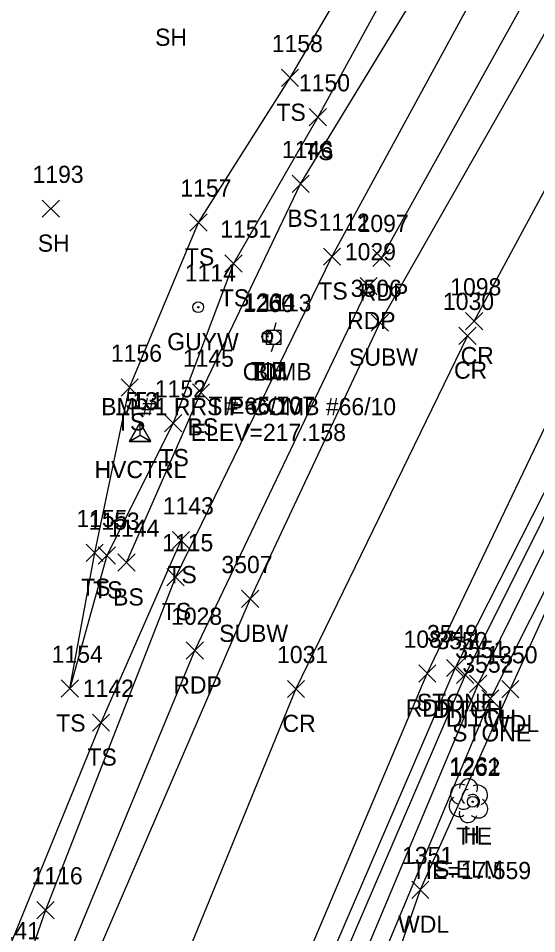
# Model space of a CAD drawing. Extents: x 1634209 to 1639641, y 608564 to 612258.
# Drawn here: x 1639421.2 to 1639481.5, y 611953 to 612059.5 of the extents above; entities that cross this region are included whole.
import ezdxf

# ---------------------------------------------------------------- set-up
doc = ezdxf.new("R2010")
doc.units = 0
for name, color, linetype in [('C_A', 7, 'Continuous'), ('C_C', 7, 'Continuous'), ('C_I', 7, 'Continuous'), ('CBP', 7, 'Continuous'), ('CPBM', 7, 'Continuous'), ('CPSM', 7, 'Continuous'), ('D_A', 7, 'Continuous'), ('D_I', 7, 'Continuous'), ('D_TIC', 7, 'Continuous'), ('DD', 7, 'Continuous'), ('L_A', 7, 'Continuous'), ('L_C', 7, 'Continuous'), ('L_I', 7, 'Continuous'), ('L_TIC', 7, 'Continuous'), ('LASF', 7, 'Continuous'), ('LAWA', 7, 'Continuous'), ('LELB', 7, 'Continuous'), ('LTD', 7, 'Continuous'), ('P_A', 7, 'Continuous'), ('P_I', 7, 'Continuous'), ('P_TIC', 7, 'Continuous'), ('PET', 7, 'Continuous'), ('PRC', 7, 'Continuous'), ('U_A', 7, 'Continuous'), ('U_C', 7, 'Continuous'), ('U_I', 7, 'Continuous'), ('U_TIC', 7, 'Continuous'), ('UP', 7, 'Continuous'), ('UPGW', 7, 'Continuous'), ('UW', 7, 'Continuous')]:
    doc.layers.add(name, color=color, linetype=linetype)

msp = doc.modelspace()

# ---------------------------------------------------------------- linework, layer by layer
at = {"layer": 'CBP'}
for centre, radius in [((1639450.18, 612022.46), 0.625), ((1639450.18, 612022.46), 0.0833), ((1639474.1, 611968.33), 0.625), ((1639474.1, 611968.33), 0.0833)]:
    msp.add_circle(centre, radius, dxfattribs=at)
at = {"layer": 'CPBM'}
for p, q in [((1639449.67, 612021.79), (1639449.67, 612022.79)), ((1639449.67, 612022.79), (1639450.67, 612022.79)), ((1639450.67, 612022.79), (1639450.67, 612021.79)), ((1639450.67, 612021.79), (1639449.67, 612021.79)), ((1639450.17, 612022.29), (1639450.17, 612022.29)), ((1639450.17, 612022.29), (1639450.17, 612022.29))]:
    msp.add_line(p, q, dxfattribs=at)
at = {"layer": 'CPSM'}
for p, q in [((1639434.12, 612010.25), (1639435.37, 612012.42)), ((1639434.13, 612010.26), (1639435.38, 612012.43)), ((1639434.13, 612010.26), (1639435.38, 612012.43)), ((1639436.62, 612010.25), (1639435.37, 612012.42)), ((1639435.37, 612010.97), (1639435.37, 612012.42)), ((1639436.63, 612010.26), (1639435.38, 612012.43)), ((1639435.38, 612010.98), (1639435.38, 612012.43)), ((1639436.63, 612010.26), (1639435.38, 612012.43)), ((1639435.38, 612010.98), (1639435.38, 612012.43)), ((1639434.12, 612010.25), (1639435.37, 612010.97)), ((1639434.12, 612010.25), (1639436.62, 612010.25)), ((1639434.13, 612010.26), (1639435.38, 612010.98)), ((1639434.13, 612010.26), (1639435.38, 612010.98)), ((1639434.13, 612010.26), (1639436.63, 612010.26)), ((1639434.13, 612010.26), (1639436.63, 612010.26)), ((1639435.37, 612010.97), (1639435.37, 612010.97)), ((1639435.37, 612010.97), (1639436.62, 612010.25)), ((1639435.38, 612010.98), (1639435.38, 612010.98)), ((1639435.38, 612010.98), (1639436.63, 612010.26)), ((1639435.38, 612010.98), (1639435.38, 612010.98)), ((1639435.38, 612010.98), (1639436.63, 612010.26))]:
    msp.add_line(p, q, dxfattribs=at)
at = {"layer": 'D_TIC'}
for points in [[(1639472.22, 611982.07), (1639474.22, 611984.07)], [(1639474.22, 611982.07), (1639472.22, 611984.07)], [(1639473.74, 611981.05), (1639475.74, 611983.05)], [(1639475.74, 611981.05), (1639473.74, 611983.05)]]:
    msp.add_lwpolyline(points, dxfattribs=at)
at = {"layer": 'DD'}
for points in [[(1639560.57, 612129.01), (1639556.53, 612119.06), (1639548.81, 612104.26), (1639529.12, 612083.62), (1639507.53, 612047.31), (1639491.18, 612019.02), (1639473.22, 611983.07), (1639456.59, 611944.52), (1639441.68, 611899.83), (1639426.6, 611855.12), (1639414, 611809.64), (1639403.11, 611769.87), (1639390.43, 611727.49), (1639379.87, 611693.81), (1639369.1, 611662.09), (1639367.84, 611659.83)], [(1639561.94, 612128.14), (1639558.11, 612117.59), (1639549.56, 612103.15), (1639530.32, 612082.73), (1639508.94, 612046.64), (1639492.68, 612018.5), (1639474.74, 611982.05), (1639458.96, 611944.55), (1639442.97, 611899.33), (1639428.64, 611854.96), (1639415.08, 611808.28), (1639405.32, 611769.46), (1639392.22, 611726.77), (1639382.52, 611693.71), (1639371.49, 611661), (1639370.19, 611658.57)]]:
    msp.add_lwpolyline(points, dxfattribs=at)
at = {"layer": 'L_TIC'}
for points in [[(1639451.83, 612051.53), (1639453.83, 612053.53)], [(1639453.83, 612051.53), (1639451.83, 612053.53)], [(1639455.07, 612046.96), (1639457.07, 612048.96)], [(1639457.07, 612046.96), (1639455.07, 612048.96)], [(1639453.06, 612039.2), (1639455.06, 612041.2)], [(1639455.06, 612039.2), (1639453.06, 612041.2)], [(1639423.98, 612036.31), (1639425.98, 612038.31)], [(1639425.98, 612036.31), (1639423.98, 612038.31)], [(1639441.18, 612034.71), (1639443.18, 612036.71)], [(1639443.18, 612034.71), (1639441.18, 612036.71)], [(1639456.71, 612030.74), (1639458.71, 612032.74)], [(1639458.71, 612030.74), (1639456.71, 612032.74)], [(1639445.25, 612029.94), (1639447.25, 612031.94)], [(1639447.25, 612029.94), (1639445.25, 612031.94)], [(1639433.15, 612015.51), (1639435.15, 612017.51)], [(1639435.15, 612015.51), (1639433.15, 612017.51)], [(1639441.46, 612014.93), (1639443.46, 612016.93)], [(1639443.46, 612014.93), (1639441.46, 612016.93)], [(1639438.22, 612011.36), (1639440.22, 612013.36)], [(1639440.22, 612011.36), (1639438.22, 612013.36)], [(1639439.14, 611997.75), (1639441.14, 611999.75)], [(1639441.14, 611997.75), (1639439.14, 611999.75)], [(1639429.09, 611996.28), (1639431.09, 611998.28)], [(1639431.09, 611996.28), (1639429.09, 611998.28)], [(1639430.5, 611995.97), (1639432.5, 611997.97)], [(1639432.5, 611995.97), (1639430.5, 611997.97)], [(1639432.79, 611995.15), (1639434.79, 611997.15)], [(1639434.79, 611995.15), (1639432.79, 611997.15)], [(1639438.5, 611993.46), (1639440.5, 611995.46)], [(1639440.5, 611993.46), (1639438.5, 611995.46)], [(1639471.04, 611982.89), (1639473.04, 611984.89)], [(1639473.04, 611982.89), (1639471.04, 611984.89)], [(1639426.2, 611980.49), (1639428.2, 611982.49)], [(1639428.2, 611980.49), (1639426.2, 611982.49)], [(1639477.47, 611980.43), (1639479.47, 611982.43)], [(1639479.47, 611980.43), (1639477.47, 611982.43)], [(1639475.15, 611979.34), (1639477.15, 611981.34)], [(1639477.15, 611979.34), (1639475.15, 611981.34)], [(1639429.83, 611976.53), (1639431.83, 611978.53)], [(1639431.83, 611976.53), (1639429.83, 611978.53)], [(1639466.99, 611957.08), (1639468.99, 611959.08)], [(1639468.99, 611957.08), (1639466.99, 611959.08)], [(1639423.36, 611954.72), (1639425.36, 611956.72)], [(1639425.36, 611954.72), (1639423.36, 611956.72)]]:
    msp.add_lwpolyline(points, dxfattribs=at)
at = {"layer": 'LASF'}
for points in [[(1639558.56, 612130.45), (1639552.86, 612120.18), (1639541.01, 612102.18), (1639527.49, 612085.59), (1639505.85, 612048.28), (1639489.98, 612019.2), (1639472.04, 611983.89), (1639455.22, 611944.85), (1639439.42, 611901.14), (1639424.97, 611855.61), (1639411.65, 611810.44), (1639400.31, 611769.99), (1639387.4, 611727.33), (1639377.22, 611693.8), (1639367.21, 611662.75), (1639359.89, 611644.2)], [(1639564.17, 612127.3), (1639559.55, 612115.01), (1639546.48, 612097.15), (1639532.98, 612081.91), (1639511.96, 612045.66), (1639494.66, 612017.18), (1639476.15, 611980.34), (1639460.76, 611943.45), (1639444.67, 611898.59), (1639430.04, 611853.19), (1639417.13, 611807.26), (1639407.25, 611767.41), (1639395.02, 611725.74), (1639384.78, 611692.04), (1639373.34, 611660.29), (1639366.81, 611640.98)]]:
    msp.add_lwpolyline(points, dxfattribs=at)
at = {"layer": 'LAWA'}
msp.add_lwpolyline([(1639621.29, 612162.67), (1639586.37, 612122.18), (1639574.47, 612128.38), (1639569.45, 612130.12), (1639568.95, 612119.64), (1639554.1, 612098.18), (1639539.81, 612087.62), (1639526.58, 612068.13), (1639518.72, 612053.78), (1639510.6, 612040.7), (1639492.01, 612011.11), (1639478.47, 611981.43), (1639467.99, 611958.08), (1639459.16, 611932.72), (1639452.06, 611918.05), (1639447.34, 611897.74), (1639441.05, 611876.68), (1639428.25, 611845.92)], dxfattribs=at)
at = {"layer": 'LELB'}
for points in [[(1639486.03, 612090.67), (1639466.52, 612067.04), (1639456.07, 612047.96), (1639446.25, 612030.94), (1639439.22, 612012.36), (1639431.5, 611996.97), (1639427.2, 611981.49), (1639430.09, 611997.28), (1639434.15, 612016.51), (1639442.18, 612035.71), (1639452.83, 612052.53), (1639468.37, 612078.96), (1639484.08, 612100.5), (1639508.75, 612130.39), (1639537.72, 612170.27), (1639559.87, 612201)], [(1639563.38, 612198.7), (1639539.24, 612164.06), (1639514.54, 612127.14), (1639495.77, 612095.8), (1639476.98, 612067.19), (1639457.71, 612031.74), (1639439.5, 611994.46), (1639424.36, 611955.72), (1639410.24, 611915.34), (1639396.62, 611874), (1639380.38, 611821.61)], [(1639433.79, 611996.15), (1639442.46, 612015.93), (1639454.06, 612040.2), (1639468.96, 612064.67)], [(1639383.1, 611838.36), (1639397.42, 611885.01), (1639407.84, 611916.5), (1639419.32, 611949.32), (1639430.83, 611977.53), (1639440.14, 611998.75)]]:
    msp.add_lwpolyline(points, dxfattribs=at)
at = {"layer": 'LTD'}
msp.add_line((1639473.57, 611968.49), (1639473.57, 611968.49), dxfattribs=at)
msp.add_line((1639473.57, 611968.49), (1639473.57, 611968.49), dxfattribs=at)
msp.add_arc((1639473.62, 611969.93), 1.05, 335.5272, 180.9563, dxfattribs=at)
for centre, major_axis, ratio, start_param, end_param in [((1639472.78, 611969.16), (1.21, -0.51), 0.895232, 1.570796, 4.712389), ((1639473.36, 611968.95), (-0.208, -0.792), 0.645439, 3.141593, 6.283185), ((1639474.61, 611969.08), (-1.14, -0.48), 0.949671, 1.570796, 4.712389), ((1639472.49, 611967.79), (0.58, -1.04), 0.959034, 3.141593, 6.283185), ((1639474.07, 611968.33), (-0.5, 0.667), 0.989748, 3.141593, 6.283185), ((1639474.57, 611967.66), (-1.09, 0.79), 0.841452, 1.570796, 4.712389), ((1639473.11, 611967.74), (-0.625, -0.083), 0.423636, 0, 3.141593), ((1639473.57, 611966.99), (0.26, 1.06), 0.942809, 1.570796, 4.712389)]:
    msp.add_ellipse(centre, major_axis=major_axis, ratio=ratio, start_param=start_param, end_param=end_param, dxfattribs=at)
at = {"layer": 'P_TIC'}
for points in [[(1639462.47, 612030.6), (1639464.47, 612032.6)], [(1639464.47, 612030.6), (1639462.47, 612032.6)], [(1639460.99, 612027.31), (1639462.99, 612029.31)], [(1639462.99, 612027.31), (1639460.99, 612029.31)], [(1639473.26, 612023.23), (1639475.26, 612025.23)], [(1639475.26, 612023.23), (1639473.26, 612025.23)], [(1639472.49, 612021.53), (1639474.49, 612023.53)], [(1639474.49, 612021.53), (1639472.49, 612023.53)], [(1639440.75, 611984.91), (1639442.75, 611986.91)], [(1639442.75, 611984.91), (1639440.75, 611986.91)], [(1639467.81, 611982.24), (1639469.81, 611984.24)], [(1639469.81, 611982.24), (1639467.81, 611984.24)], [(1639452.52, 611980.45), (1639454.52, 611982.45)], [(1639454.52, 611980.45), (1639452.52, 611982.45)]]:
    msp.add_lwpolyline(points, dxfattribs=at)
at = {"layer": 'PET'}
for points in [[(1639566.82, 612196.97), (1639540.89, 612159.33), (1639514.14, 612118.57), (1639490.67, 612080.46), (1639463.47, 612031.6)], [(1639245.26, 611428.04), (1639265.27, 611462.65), (1639285.72, 611496.98), (1639297.96, 611518.63), (1639312.46, 611545.86), (1639331.24, 611585.47), (1639351.91, 611632.95), (1639369.29, 611681.55), (1639385.15, 611732.94), (1639399.72, 611782.78), (1639415.55, 611836.4), (1639431.27, 611887.12), (1639449.51, 611937.71), (1639468.81, 611983.24), (1639484.71, 612016.46), (1639503.95, 612051.42), (1639527.63, 612090.72), (1639556.4, 612135.38), (1639588.32, 612182.52)], [(1639220.96, 611441.47), (1639247.22, 611483.75), (1639268.21, 611519.52), (1639285.57, 611551.38), (1639309.59, 611600.33), (1639328.5, 611645.78), (1639344.08, 611688.66), (1639358.64, 611735.43), (1639372.55, 611782.94), (1639389.96, 611841.92), (1639405.55, 611892.01), (1639422.64, 611939.83), (1639441.75, 611985.91), (1639461.99, 612028.31)]]:
    msp.add_lwpolyline(points, dxfattribs=at)
at = {"layer": 'PRC'}
for points in [[(1639474.26, 612024.23), (1639486.3, 612046.51), (1639504.13, 612077.19), (1639528.27, 612115.93), (1639556.35, 612158.67), (1639577.48, 612189.8)], [(1639473.49, 612022.53), (1639453.52, 611981.45), (1639432.7, 611930.67), (1639416.88, 611885.46), (1639401.13, 611834.82), (1639385.48, 611780.16), (1639369.66, 611726.72), (1639353.84, 611677.52), (1639335.57, 611627.61), (1639314.72, 611580.03), (1639292.65, 611536.14), (1639275.3, 611504.78), (1639250.46, 611462.84), (1639222.36, 611418.18)]]:
    msp.add_lwpolyline(points, dxfattribs=at)
at = {"layer": 'U_TIC'}
for points in [[(1639462.29, 612023.05), (1639464.29, 612025.05)], [(1639464.29, 612023.05), (1639462.29, 612025.05)], [(1639447.18, 611990.92), (1639449.18, 611992.92)], [(1639449.18, 611990.92), (1639447.18, 611992.92)]]:
    msp.add_lwpolyline(points, dxfattribs=at)
at = {"layer": 'UP'}
for p, q in [((1639451.18, 612024.02), (1639450.93, 612023.19)), ((1639450.1, 612021.52), (1639450.1, 612023.19)), ((1639450.1, 612023.19), (1639451.77, 612023.19)), ((1639451.77, 612023.19), (1639451.77, 612021.52)), ((1639450.93, 612022.36), (1639450.93, 612022.36)), ((1639451.77, 612021.52), (1639450.1, 612021.52)), ((1639450.68, 612020.69), (1639450.93, 612021.52))]:
    msp.add_line(p, q, dxfattribs=at)
msp.add_circle((1639450.93, 612022.36), 0.833, dxfattribs=at)
at = {"layer": 'UPGW'}
for radius in [0.625, 0.0833]:
    msp.add_circle((1639442.14, 612025.85), radius, dxfattribs=at)
at = {"layer": 'UW'}
msp.add_lwpolyline([(1639594.99, 612226.51), (1639569.63, 612190.35), (1639550.67, 612164.48), (1639527.14, 612128.9), (1639506.92, 612097.5), (1639485.03, 612062.24), (1639463.29, 612024.05), (1639448.18, 611991.92), (1639428.21, 611945.59), (1639409.39, 611896.28), (1639395.47, 611852.57), (1639388.14, 611826.68), (1639366.36, 611747.21), (1639350.92, 611692.02), (1639316.38, 611597.42), (1639292.15, 611550.99), (1639279.15, 611528.72), (1639253.95, 611487.01), (1639229.78, 611449.06), (1639200.46, 611402.5), (1639172.27, 611358.67), (1639148.82, 611320.98)], dxfattribs=at)

# ---------------------------------------------------------------- texts
at = {"layer": 'C_A'}
for s, p in [('TIE', (1639448.26, 612017.46)), ('BM', (1639448.49, 612017.29)), ('HVCTRL', (1639430.06, 612005.97)), ('HVCTRL', (1639430.07, 612005.98)), ('HVCTRL', (1639430.07, 612005.98)), ('TIE', (1639472.18, 611963.33))]:
    msp.add_text(s, height=2, dxfattribs=at).set_placement(p)
at = {"layer": 'C_C'}
for s, p in [('BM #1 RRSIP COMB #66/10', (1639430.84, 612013.29)), ('TIE=5.707', (1639443.33, 612013.46)), ('ELEV=217.158', (1639441.27, 612010.29)), ('TIE=17.559', (1639466.99, 611959.33))]:
    msp.add_text(s, height=2, dxfattribs=at).set_placement(p)
at = {"layer": 'C_I'}
for s, p in [('1260', (1639447.34, 612025.29)), ('1264', (1639447.44, 612025.46)), ('5_1', (1639433.66, 612013.98)), ('13', (1639434.47, 612013.97)), ('5', (1639434.81, 612013.98)), ('1262', (1639471.36, 611971.33))]:
    msp.add_text(s, height=2, dxfattribs=at).set_placement(p)
at = {"layer": 'D_A'}
for p in [(1639469.46, 611978.07), (1639470.98, 611977.05)]:
    msp.add_text('DITCH', height=2, dxfattribs=at).set_placement(p)
at = {"layer": 'D_I'}
for s, p in [('3550', (1639469.87, 611986.07)), ('3551', (1639472.05, 611985.05))]:
    msp.add_text(s, height=2, dxfattribs=at).set_placement(p)
at = {"layer": 'L_A'}
for s, p in [('SH', (1639437.12, 612056.26)), ('TS', (1639451.24, 612047.53)), ('TS', (1639454.48, 612042.96)), ('BS', (1639452.51, 612035.2)), ('SH', (1639423.46, 612032.31)), ('TS', (1639440.59, 612030.71)), ('TS', (1639456.12, 612026.74)), ('TS', (1639444.66, 612025.94)), ('TS', (1639432.56, 612011.51)), ('BS', (1639440.9, 612010.93)), ('TS', (1639437.63, 612007.36)), ('TS', (1639438.55, 611993.75)), ('TS', (1639428.5, 611992.28)), ('TS', (1639429.91, 611991.97)), ('BS', (1639432.23, 611991.15)), ('TS', (1639437.91, 611989.46)), ('STONE', (1639467.59, 611978.89)), ('TS', (1639425.61, 611976.49)), ('WDL', (1639475.88, 611976.43)), ('STONE', (1639471.69, 611975.34)), ('TS', (1639429.24, 611972.53)), ('H', (1639473, 611963.49)), ('WDL', (1639465.41, 611953.08))]:
    msp.add_text(s, height=2, dxfattribs=at).set_placement(p)
at = {"layer": 'L_C'}
msp.add_text('S.ELM', height=2, dxfattribs=at).set_placement((1639469.6, 611959.49))
at = {"layer": 'L_I'}
for s, p in [('1158', (1639450.7, 612055.53)), ('1150', (1639453.86, 612050.96)), ('1146', (1639451.88, 612043.2)), ('1193', (1639422.85, 612040.31)), ('1157', (1639440.06, 612038.71)), ('1112', (1639456.15, 612034.74)), ('1151', (1639444.7, 612033.94)), ('1156', (1639431.97, 612019.51)), ('1145', (1639440.34, 612018.93)), ('1152', (1639437.09, 612015.36)), ('1143', (1639438.01, 612001.75)), ('1155', (1639427.96, 612000.28)), ('1153', (1639429.37, 611999.97)), ('1144', (1639431.67, 611999.15)), ('1115', (1639437.94, 611997.46)), ('3549', (1639468.77, 611986.89)), ('1154', (1639425.08, 611984.49)), ('1350', (1639475.69, 611984.43)), ('3552', (1639472.89, 611983.34)), ('1142', (1639428.7, 611980.53)), ('1261', (1639471.4, 611971.49)), ('1351', (1639465.87, 611961.08)), ('1116', (1639422.74, 611958.72)), ('1141', (1639417.76, 611952.32))]:
    msp.add_text(s, height=2, dxfattribs=at).set_placement(p)
at = {"layer": 'P_A'}
for s, p in [('RDP', (1639460.95, 612026.6)), ('RDP', (1639459.47, 612023.31)), ('CR', (1639472.69, 612019.23)), ('CR', (1639471.92, 612017.53)), ('RDP', (1639439.24, 611980.91)), ('RDP', (1639466.29, 611978.24)), ('CR', (1639451.95, 611976.45))]:
    msp.add_text(s, height=2, dxfattribs=at).set_placement(p)
at = {"layer": 'P_I'}
for s, p in [('1097', (1639460.69, 612034.6)), ('1029', (1639459.21, 612031.31)), ('1098', (1639471.48, 612027.23)), ('1030', (1639470.63, 612025.53)), ('1028', (1639438.98, 611988.91)), ('1087', (1639466.04, 611986.24)), ('1031', (1639451.32, 611984.45))]:
    msp.add_text(s, height=2, dxfattribs=at).set_placement(p)
at = {"layer": 'U_A'}
for s, p in [('GUYW', (1639438.53, 612020.85)), ('SUBW', (1639459.7, 612019.05)), ('COMB', (1639447.32, 612017.36)), ('SUBW', (1639444.58, 611986.92))]:
    msp.add_text(s, height=2, dxfattribs=at).set_placement(p)
at = {"layer": 'U_C'}
msp.add_text('# 66/10', height=2, dxfattribs=at).set_placement((1639445.29, 612013.36))
at = {"layer": 'U_I'}
for s, p in [('1114', (1639440.58, 612028.85)), ('3506', (1639459.89, 612027.05)), ('1113', (1639449.38, 612025.36)), ('3507', (1639444.84, 611994.92))]:
    msp.add_text(s, height=2, dxfattribs=at).set_placement(p)

doc.saveas('drawing.dxf')
